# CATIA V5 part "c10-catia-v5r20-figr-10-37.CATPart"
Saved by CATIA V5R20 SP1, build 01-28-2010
Part number: Part1
Bounding box of the stored display mesh (mm): x -322.306 to 0, y -118.205 to 88.531, z 0 to 101.949
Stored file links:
  D:\v5_r20\psrt_files_downloaded\c10\c10-catia-v5r20-figr-10-37.CATPart
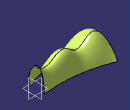
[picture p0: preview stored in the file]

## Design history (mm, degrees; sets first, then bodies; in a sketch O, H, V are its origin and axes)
Set1
  Curve1: Elements (vertex of Sketch2; vertex of Sketch1; vertex of Sketch3)
  Loft1: Sections (Sketch4; Curve1), Guides (Sketch2; Sketch1; Sketch3)
Body1 (main body)
  Sketch1 on zx-plane, origin (0, 0, 0), H (-1, 0, 0), V (0, 0, 1)
    spline S1 through (0, 96.336) (70.1946, 72.4244) (144.1119, 96.336) (203.5098, 63.985) (253.668, 92.1163) (322.3056, 72.4244)
    point P1 (0, 96.336)
    coincidence: P1 V
  Sketch2 on xy-plane, origin (0, 0, 0), H (1, 0, 0), V (0, 1, 0)
    point P1 (0, 47.0553)
    arc A1 centre (-78.7604, 671.3501) radius 629.2433 from (0, 47.0553) to (-315.9706, 88.5306) cw
    coincidence: P1 V
  Sketch3 on xy-plane, origin (0, 0, 0), H (1, 0, 0), V (0, 1, 0)
    line L1 (0, -26.5991) -> (-311.8959, -118.2048)
    point P1 (0, -26.5991)
    coincidence: P1 V
  Sketch4 on yz-plane, origin (0, 0, 0), H (0, 1, 0), V (0, 0, 1)
    point P1 (-26.5991, 0)
    point P2 (0, 58.544)
    point P3 (47.0553, 0)
    reference projected point E1 (47.0553, 0) from vertex of Sketch2
    reference projected point E2 (-26.5991, 0) from vertex of Sketch3
    spline S1 through (-26.5991, 0) (-29.9268, 35.6209) (0, 96.336) (47.0553, 0)
    reference projected point E3 (0, 96.336) from vertex of Sketch1
    point P4 (-26.5991, 0)
    point P5 (0, 96.336)
    point P6 (47.0553, 0)
    coincidence: P1 H, P3 H, E1 P3, P1 E2, P4 P1, P5 V, P6 P3, E3 S1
